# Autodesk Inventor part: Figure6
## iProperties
Author: CADSoft
Shininess: 77.0
Angle Display Precision: 2
Document Length Units: 11269
Document Angle Units: 11283
Document Time Units: 11279
Document Mass Units: 11290
Document Length Units Precision: 3
Document Angle Units Precision: 2
Compacted: False
PropertySet Name: _Private Model Information
Created: 2002-01
Part Number: Figure6
Document SubType Name: Modeling
Designer: CADSoft
Control State: 0
Master: False
Checked Out: False
PropertySet Name: Design Tracking Control
Density: 0.0
Volumn: 0.0
Area: 0.0
PropertySet Name: Model Information
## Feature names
1. Extrusion2
2. Coil4
